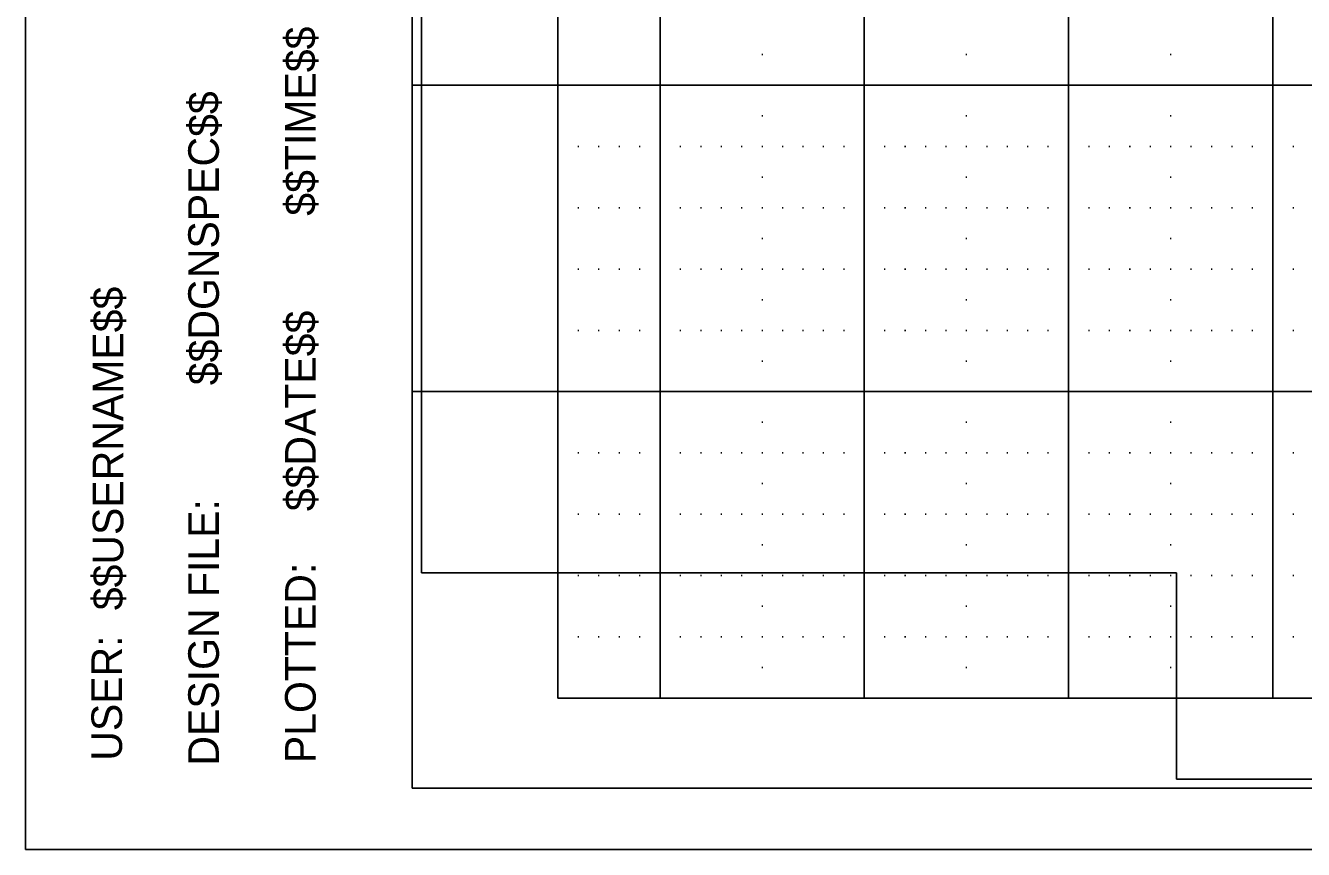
# Model space of a CAD drawing. Extents: x -1.3 to 32, y -0.2 to 20.7.
# Drawn here: x -1.292 to 2.879, y -0.229 to 2.458 of the extents above; entities that cross this region are included whole.
import ezdxf

# ---------------------------------------------------------------- set-up
doc = ezdxf.new("R2010")
doc.units = 0
for name, color, linetype in [('Level 1', 7, 'Continuous'), ('Level 37', 7, 'Continuous'), ('Level 4', 7, 'Continuous'), ('Level 5', 7, 'Continuous'), ('Level 62', 7, 'Continuous'), ('Level 63', 7, 'Continuous')]:
    doc.layers.add(name, color=color, linetype=linetype)

msp = doc.modelspace()

# ---------------------------------------------------------------- linework, layer by layer
at = {"layer": 'Level 1'}
for p, q in [((-0.03, -0.03), (-0.03, 20.516)), ((31.588, -0.03), (-0.03, -0.03))]:
    msp.add_line(p, q, dxfattribs=at)
at = {"layer": 'Level 37'}
for p, q in [((0.4457, 0.2635), (0.4457, 10.264)), ((0.7787, 0.2635), (0.4457, 0.2635)), ((31.1123, 0.264), (0.7787, 0.2635)), ((0.7787, 0.2635), (0.7787, 0.2635))]:
    msp.add_line(p, q, dxfattribs=at)
at = {"layer": 'Level 4'}
for p, q in [((0.4457, 0.264), (0.4457, 10.264)), ((0.779, 0.264), (0.779, 10.264)), ((1.4457, 0.264), (1.4457, 10.264)), ((2.1123, 0.264), (2.1123, 10.264)), ((2.779, 0.264), (2.779, 10.264)), ((31.588, 2.264), (-0.03, 2.264)), ((31.588, 1.264), (-0.03, 1.264)), ((31.588, 0.264), (0.4456, 0.264))]:
    msp.add_line(p, q, dxfattribs=at)
at = {"layer": 'Level 5'}
for p, q in [((1.1107, 2.364), (1.114, 2.364)), ((1.7773, 2.364), (1.7807, 2.364)), ((2.444, 2.364), (2.4473, 2.364)), ((1.1107, 2.164), (1.114, 2.164)), ((1.7773, 2.164), (1.7807, 2.164)), ((2.444, 2.164), (2.4473, 2.164)), ((0.5107, 2.064), (0.514, 2.064)), ((0.5773, 2.064), (0.5807, 2.064)), ((0.644, 2.064), (0.6473, 2.064)), ((0.7107, 2.064), (0.714, 2.064)), ((0.844, 2.064), (0.8473, 2.064)), ((0.9107, 2.064), (0.914, 2.064)), ((0.9773, 2.064), (0.9807, 2.064)), ((1.044, 2.064), (1.0473, 2.064)), ((1.1107, 2.064), (1.114, 2.064)), ((1.1773, 2.064), (1.1807, 2.064)), ((1.244, 2.064), (1.2473, 2.064)), ((1.3107, 2.064), (1.314, 2.064)), ((1.3773, 2.064), (1.3807, 2.064)), ((1.5107, 2.064), (1.514, 2.064)), ((1.5773, 2.064), (1.5807, 2.064)), ((1.644, 2.064), (1.6473, 2.064)), ((1.7107, 2.064), (1.714, 2.064)), ((1.7773, 2.064), (1.7807, 2.064)), ((1.844, 2.064), (1.8473, 2.064)), ((1.9107, 2.064), (1.914, 2.064)), ((1.9773, 2.064), (1.9807, 2.064)), ((2.044, 2.064), (2.0473, 2.064)), ((2.1773, 2.064), (2.1807, 2.064)), ((2.244, 2.064), (2.2473, 2.064)), ((2.3107, 2.064), (2.314, 2.064)), ((2.3773, 2.064), (2.3807, 2.064)), ((2.444, 2.064), (2.4473, 2.064)), ((2.5107, 2.064), (2.514, 2.064)), ((2.5773, 2.064), (2.5807, 2.064)), ((2.644, 2.064), (2.6473, 2.064)), ((2.7107, 2.064), (2.714, 2.064)), ((2.844, 2.064), (2.8473, 2.064)), ((1.1107, 1.964), (1.114, 1.964)), ((1.7773, 1.964), (1.7807, 1.964)), ((2.444, 1.964), (2.4473, 1.964)), ((0.5107, 1.864), (0.514, 1.864)), ((0.5773, 1.864), (0.5807, 1.864)), ((0.644, 1.864), (0.6473, 1.864)), ((0.7107, 1.864), (0.714, 1.864)), ((0.844, 1.864), (0.8473, 1.864)), ((0.9107, 1.864), (0.914, 1.864)), ((0.9773, 1.864), (0.9807, 1.864)), ((1.044, 1.864), (1.0473, 1.864)), ((1.1107, 1.864), (1.114, 1.864)), ((1.1773, 1.864), (1.1807, 1.864)), ((1.244, 1.864), (1.2473, 1.864)), ((1.3107, 1.864), (1.314, 1.864)), ((1.3773, 1.864), (1.3807, 1.864)), ((1.5107, 1.864), (1.514, 1.864)), ((1.5773, 1.864), (1.5807, 1.864)), ((1.644, 1.864), (1.6473, 1.864)), ((1.7107, 1.864), (1.714, 1.864)), ((1.7773, 1.864), (1.7807, 1.864)), ((1.844, 1.864), (1.8473, 1.864)), ((1.9107, 1.864), (1.914, 1.864)), ((1.9773, 1.864), (1.9807, 1.864)), ((2.044, 1.864), (2.0473, 1.864)), ((2.1773, 1.864), (2.1807, 1.864)), ((2.244, 1.864), (2.2473, 1.864)), ((2.3107, 1.864), (2.314, 1.864)), ((2.3773, 1.864), (2.3807, 1.864)), ((2.444, 1.864), (2.4473, 1.864)), ((2.5107, 1.864), (2.514, 1.864)), ((2.5773, 1.864), (2.5807, 1.864)), ((2.644, 1.864), (2.6473, 1.864)), ((2.7107, 1.864), (2.714, 1.864)), ((2.844, 1.864), (2.8473, 1.864)), ((1.1107, 1.764), (1.114, 1.764)), ((1.7773, 1.764), (1.7807, 1.764)), ((2.444, 1.764), (2.4473, 1.764)), ((0.5107, 1.664), (0.514, 1.664)), ((0.5773, 1.664), (0.5807, 1.664)), ((0.644, 1.664), (0.6473, 1.664)), ((0.7107, 1.664), (0.714, 1.664)), ((0.844, 1.664), (0.8473, 1.664)), ((0.9107, 1.664), (0.914, 1.664)), ((0.9773, 1.664), (0.9807, 1.664)), ((1.044, 1.664), (1.0473, 1.664)), ((1.1107, 1.664), (1.114, 1.664)), ((1.1773, 1.664), (1.1807, 1.664)), ((1.244, 1.664), (1.2473, 1.664)), ((1.3107, 1.664), (1.314, 1.664)), ((1.3773, 1.664), (1.3807, 1.664)), ((1.5107, 1.664), (1.514, 1.664)), ((1.5773, 1.664), (1.5807, 1.664)), ((1.644, 1.664), (1.6473, 1.664)), ((1.7107, 1.664), (1.714, 1.664)), ((1.7773, 1.664), (1.7807, 1.664)), ((1.844, 1.664), (1.8473, 1.664)), ((1.9107, 1.664), (1.914, 1.664)), ((1.9773, 1.664), (1.9807, 1.664)), ((2.044, 1.664), (2.0473, 1.664)), ((2.1773, 1.664), (2.1807, 1.664)), ((2.244, 1.664), (2.2473, 1.664)), ((2.3107, 1.664), (2.314, 1.664)), ((2.3773, 1.664), (2.3807, 1.664)), ((2.444, 1.664), (2.4473, 1.664)), ((2.5107, 1.664), (2.514, 1.664)), ((2.5773, 1.664), (2.5807, 1.664)), ((2.644, 1.664), (2.6473, 1.664)), ((2.7107, 1.664), (2.714, 1.664)), ((2.844, 1.664), (2.8473, 1.664)), ((1.1107, 1.564), (1.114, 1.564)), ((1.7773, 1.564), (1.7807, 1.564)), ((2.444, 1.564), (2.4473, 1.564)), ((0.5107, 1.464), (0.514, 1.464)), ((0.5773, 1.464), (0.5807, 1.464)), ((0.644, 1.464), (0.6473, 1.464)), ((0.7107, 1.464), (0.714, 1.464)), ((0.844, 1.464), (0.8473, 1.464)), ((0.9107, 1.464), (0.914, 1.464)), ((0.9773, 1.464), (0.9807, 1.464)), ((1.044, 1.464), (1.0473, 1.464)), ((1.1107, 1.464), (1.114, 1.464)), ((1.1773, 1.464), (1.1807, 1.464)), ((1.244, 1.464), (1.2473, 1.464)), ((1.3107, 1.464), (1.314, 1.464)), ((1.3773, 1.464), (1.3807, 1.464)), ((1.5107, 1.464), (1.514, 1.464)), ((1.5773, 1.464), (1.5807, 1.464)), ((1.644, 1.464), (1.6473, 1.464)), ((1.7107, 1.464), (1.714, 1.464)), ((1.7773, 1.464), (1.7807, 1.464)), ((1.844, 1.464), (1.8473, 1.464)), ((1.9107, 1.464), (1.914, 1.464)), ((1.9773, 1.464), (1.9807, 1.464)), ((2.044, 1.464), (2.0473, 1.464)), ((2.1773, 1.464), (2.1807, 1.464)), ((2.244, 1.464), (2.2473, 1.464)), ((2.3107, 1.464), (2.314, 1.464)), ((2.3773, 1.464), (2.3807, 1.464)), ((2.444, 1.464), (2.4473, 1.464)), ((2.5107, 1.464), (2.514, 1.464)), ((2.5773, 1.464), (2.5807, 1.464)), ((2.644, 1.464), (2.6473, 1.464)), ((2.7107, 1.464), (2.714, 1.464)), ((2.844, 1.464), (2.8473, 1.464)), ((1.1107, 1.364), (1.114, 1.364)), ((1.7773, 1.364), (1.7807, 1.364)), ((2.444, 1.364), (2.4473, 1.364)), ((1.1107, 1.264), (1.114, 1.264)), ((1.7773, 1.264), (1.7807, 1.264)), ((2.444, 1.264), (2.4473, 1.264)), ((1.1107, 1.164), (1.114, 1.164)), ((1.7773, 1.164), (1.7807, 1.164)), ((2.444, 1.164), (2.4473, 1.164)), ((0.5107, 1.064), (0.514, 1.064)), ((0.5773, 1.064), (0.5807, 1.064)), ((0.644, 1.064), (0.6473, 1.064)), ((0.7107, 1.064), (0.714, 1.064)), ((0.844, 1.064), (0.8473, 1.064)), ((0.9107, 1.064), (0.914, 1.064)), ((0.9773, 1.064), (0.9807, 1.064)), ((1.044, 1.064), (1.0473, 1.064)), ((1.1107, 1.064), (1.114, 1.064)), ((1.1773, 1.064), (1.1807, 1.064)), ((1.244, 1.064), (1.2473, 1.064)), ((1.3107, 1.064), (1.314, 1.064)), ((1.3773, 1.064), (1.3807, 1.064)), ((1.5107, 1.064), (1.514, 1.064)), ((1.5773, 1.064), (1.5807, 1.064)), ((1.644, 1.064), (1.6473, 1.064)), ((1.7107, 1.064), (1.714, 1.064)), ((1.7773, 1.064), (1.7807, 1.064)), ((1.844, 1.064), (1.8473, 1.064)), ((1.9107, 1.064), (1.914, 1.064)), ((1.9773, 1.064), (1.9807, 1.064)), ((2.044, 1.064), (2.0473, 1.064)), ((2.1773, 1.064), (2.1807, 1.064)), ((2.244, 1.064), (2.2473, 1.064)), ((2.3107, 1.064), (2.314, 1.064)), ((2.3773, 1.064), (2.3807, 1.064)), ((2.444, 1.064), (2.4473, 1.064)), ((2.5107, 1.064), (2.514, 1.064)), ((2.5773, 1.064), (2.5807, 1.064)), ((2.644, 1.064), (2.6473, 1.064)), ((2.7107, 1.064), (2.714, 1.064)), ((2.844, 1.064), (2.8473, 1.064)), ((1.1107, 0.964), (1.114, 0.964)), ((1.7773, 0.964), (1.7807, 0.964)), ((2.444, 0.964), (2.4473, 0.964)), ((0.5107, 0.864), (0.514, 0.864)), ((0.5773, 0.864), (0.5807, 0.864)), ((0.644, 0.864), (0.6473, 0.864)), ((0.7107, 0.864), (0.714, 0.864)), ((0.844, 0.864), (0.8473, 0.864)), ((0.9107, 0.864), (0.914, 0.864)), ((0.9773, 0.864), (0.9807, 0.864)), ((1.044, 0.864), (1.0473, 0.864)), ((1.1107, 0.864), (1.114, 0.864)), ((1.1773, 0.864), (1.1807, 0.864)), ((1.244, 0.864), (1.2473, 0.864)), ((1.3107, 0.864), (1.314, 0.864)), ((1.3773, 0.864), (1.3807, 0.864)), ((1.5107, 0.864), (1.514, 0.864)), ((1.5773, 0.864), (1.5807, 0.864)), ((1.644, 0.864), (1.6473, 0.864)), ((1.7107, 0.864), (1.714, 0.864)), ((1.7773, 0.864), (1.7807, 0.864)), ((1.844, 0.864), (1.8473, 0.864)), ((1.9107, 0.864), (1.914, 0.864)), ((1.9773, 0.864), (1.9807, 0.864)), ((2.044, 0.864), (2.0473, 0.864)), ((2.1773, 0.864), (2.1807, 0.864)), ((2.244, 0.864), (2.2473, 0.864)), ((2.3107, 0.864), (2.314, 0.864)), ((2.3773, 0.864), (2.3807, 0.864)), ((2.444, 0.864), (2.4473, 0.864)), ((2.5107, 0.864), (2.514, 0.864)), ((2.5773, 0.864), (2.5807, 0.864)), ((2.644, 0.864), (2.6473, 0.864)), ((2.7107, 0.864), (2.714, 0.864)), ((2.844, 0.864), (2.8473, 0.864)), ((1.1107, 0.764), (1.114, 0.764)), ((1.7773, 0.764), (1.7807, 0.764)), ((2.444, 0.764), (2.4473, 0.764)), ((0.5107, 0.664), (0.514, 0.664)), ((0.5773, 0.664), (0.5807, 0.664)), ((0.644, 0.664), (0.6473, 0.664)), ((0.7107, 0.664), (0.714, 0.664)), ((0.844, 0.664), (0.8473, 0.664)), ((0.9107, 0.664), (0.914, 0.664)), ((0.9773, 0.664), (0.9807, 0.664)), ((1.044, 0.664), (1.0473, 0.664)), ((1.1107, 0.664), (1.114, 0.664)), ((1.1773, 0.664), (1.1807, 0.664)), ((1.244, 0.664), (1.2473, 0.664)), ((1.3107, 0.664), (1.314, 0.664)), ((1.3773, 0.664), (1.3807, 0.664)), ((1.5107, 0.664), (1.514, 0.664)), ((1.5773, 0.664), (1.5807, 0.664)), ((1.644, 0.664), (1.6473, 0.664)), ((1.7107, 0.664), (1.714, 0.664)), ((1.7773, 0.664), (1.7807, 0.664)), ((1.844, 0.664), (1.8473, 0.664)), ((1.9107, 0.664), (1.914, 0.664)), ((1.9773, 0.664), (1.9807, 0.664)), ((2.044, 0.664), (2.0473, 0.664)), ((2.1773, 0.664), (2.1807, 0.664)), ((2.244, 0.664), (2.2473, 0.664)), ((2.3107, 0.664), (2.314, 0.664)), ((2.3773, 0.664), (2.3807, 0.664)), ((2.444, 0.664), (2.4473, 0.664)), ((2.5107, 0.664), (2.514, 0.664)), ((2.5773, 0.664), (2.5807, 0.664)), ((2.644, 0.664), (2.6473, 0.664)), ((2.7107, 0.664), (2.714, 0.664)), ((2.844, 0.664), (2.8473, 0.664)), ((1.1107, 0.564), (1.114, 0.564)), ((1.7773, 0.564), (1.7807, 0.564)), ((2.444, 0.564), (2.4473, 0.564)), ((0.5107, 0.464), (0.514, 0.464)), ((0.5773, 0.464), (0.5807, 0.464)), ((0.644, 0.464), (0.6473, 0.464)), ((0.7107, 0.464), (0.714, 0.464)), ((0.844, 0.464), (0.8473, 0.464)), ((0.9107, 0.464), (0.914, 0.464)), ((0.9773, 0.464), (0.9807, 0.464)), ((1.044, 0.464), (1.0473, 0.464)), ((1.1107, 0.464), (1.114, 0.464)), ((1.1773, 0.464), (1.1807, 0.464)), ((1.244, 0.464), (1.2473, 0.464)), ((1.3107, 0.464), (1.314, 0.464)), ((1.3773, 0.464), (1.3807, 0.464)), ((1.5107, 0.464), (1.514, 0.464)), ((1.5773, 0.464), (1.5807, 0.464)), ((1.644, 0.464), (1.6473, 0.464)), ((1.7107, 0.464), (1.714, 0.464)), ((1.7773, 0.464), (1.7807, 0.464)), ((1.844, 0.464), (1.8473, 0.464)), ((1.9107, 0.464), (1.914, 0.464)), ((1.9773, 0.464), (1.9807, 0.464)), ((2.044, 0.464), (2.0473, 0.464)), ((2.1773, 0.464), (2.1807, 0.464)), ((2.244, 0.464), (2.2473, 0.464)), ((2.3107, 0.464), (2.314, 0.464)), ((2.3773, 0.464), (2.3807, 0.464)), ((2.444, 0.464), (2.4473, 0.464)), ((2.5107, 0.464), (2.514, 0.464)), ((2.5773, 0.464), (2.5807, 0.464)), ((2.644, 0.464), (2.6473, 0.464)), ((2.7107, 0.464), (2.714, 0.464)), ((2.844, 0.464), (2.8473, 0.464)), ((1.1107, 0.364), (1.114, 0.364)), ((1.7773, 0.364), (1.7807, 0.364)), ((2.444, 0.364), (2.4473, 0.364))]:
    msp.add_line(p, q, dxfattribs=at)
at = {"layer": 'Level 62'}
for p, q in [((0, 10.294), (0, 0.6734)), ((0, 0.6734), (2.4642, 0.6734)), ((2.4642, 0.6734), (2.4642, 0)), ((2.4642, 0), (31.618, 0))]:
    msp.add_line(p, q, dxfattribs=at)
at = {"layer": 'Level 63'}
msp.add_lwpolyline([(-1.292, -0.2295), (32.038, -0.2295), (32.038, 20.7175), (-1.292, 20.7175)], close=True, dxfattribs=at)

# ---------------------------------------------------------------- texts
at = {"layer": 'Level 1'}
for s, height, p in [('$$TIME$$', 0.1, (-0.345, 1.838)), ('$$DGNSPEC$$', 0.100002, (-0.661, 1.285)), ('$$USERNAME$$', 0.100002, (-0.973, 0.551)), ('$$DATE$$', 0.1, (-0.345, 0.874)), ('DESIGN FILE:', 0.100002, (-0.661, 0.044)), ('PLOTTED:', 0.1, (-0.345, 0.052)), ('USER:', 0.1, (-0.977, 0.06))]:
    msp.add_text(s, height=height, rotation=90, dxfattribs=at).set_placement(p)

doc.saveas('drawing.dxf')
